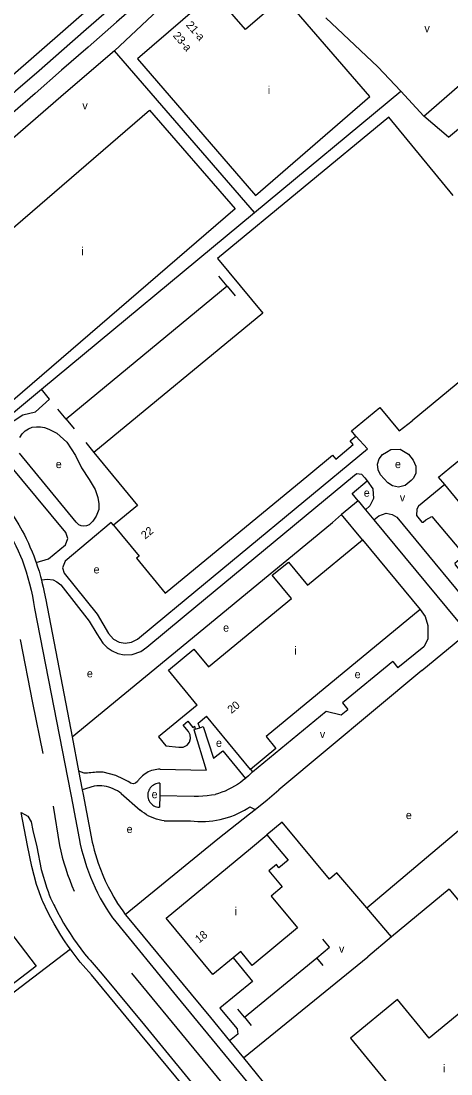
# Model space of a CAD drawing. Extents: x 156097 to 158136, y 385644 to 388348.
# Drawn here: x 156805 to 157020, y 386636 to 387162 of the extents above; entities that cross this region are included whole.
import ezdxf

# ---------------------------------------------------------------- set-up
doc = ezdxf.new("R2010")
doc.units = 0
for name, color, linetype in [('BLT_Basislijn', 7, 'Continuous'), ('BLT_Bebouwing', 7, 'Continuous'), ('BLT_Centroide', 7, 'Continuous'), ('BLT_Huisnummer', 7, 'Continuous'), ('BLT_Huisnummer_reeks', 7, 'Continuous')]:
    doc.layers.add(name, color=color, linetype=linetype)

msp = doc.modelspace()

# ---------------------------------------------------------------- linework, layer by layer
at = {"layer": 'BLT_Basislijn'}
for p, q in [((156921.57, 387066.28), (156851.67, 387147.13)), ((157006.17, 387114.42), (157045.55, 387148.73)), ((156921.57, 387066.28), (156994.69, 387126.94)), ((156815.18, 386977.97), (156921.57, 387066.28)), ((156907.94, 387029.51), (156827.49, 386963.06)), ((156907.94, 387029.51), (156903.87, 387034.43)), ((156907.94, 387029.51), (156912.01, 387024.58)), ((156774.73, 386944.4), (156815.18, 386977.97)), ((156827.49, 386963.06), (156823.42, 386967.99)), ((156827.49, 386963.06), (156831.56, 386958.13)), ((156837.34, 386951.28), (156841.4, 386946.35)), ((156886.56, 386864.54), (156971.62, 386935.07)), ((156973.42, 386922.21), (156965.17, 386915.31)), ((156973.42, 386922.21), (156977.12, 386917.72)), ((156975.66, 386902.77), (156965.17, 386915.31)), ((156977.12, 386917.72), (156981.2, 386912.78)), ((156937.74, 386892.59), (156960.55, 386911.45)), ((156981.2, 386912.78), (157028.02, 386856.23)), ((156929.48, 386885.76), (156937.74, 386892.59)), ((156893.5, 386856.13), (156929.48, 386885.76)), ((156811.8, 386868.47), (156821.48, 386818.91)), ((156830.51, 386804.26), (156893.5, 386856.13)), ((157005.2, 386837.49), (157028.02, 386856.23)), ((156990.73, 386841.92), (156965.6, 386821.21)), ((156990.73, 386841.92), (156993.29, 386838.81)), ((157005.2, 386837.49), (156933.74, 386777.74)), ((156821.48, 386818.91), (156831.03, 386769.38)), ((156965.6, 386821.21), (156968.28, 386817.96)), ((156920.69, 386786.76), (156957.5, 386817.1)), ((156957.5, 386817.1), (156964.97, 386815.21)), ((156830.51, 386804.26), (156833.79, 386787.32)), ((156833.79, 386787.32), (156835.59, 386777.84)), ((156874.59, 386788.06), (156897.42, 386787.68)), ((156841.49, 386779.56), (156835.59, 386777.84)), ((156835.59, 386777.84), (156836.07, 386775.41)), ((156874.42, 386781.08), (156874.33, 386774.94)), ((156927.96, 386772.86), (156933.74, 386777.74)), ((156836.07, 386775.41), (156840.62, 386751.7)), ((156855.08, 386775.94), (156864.57, 386767.64)), ((156874.33, 386774.94), (156874.24, 386769.07)), ((156874.33, 386774.94), (156891.45, 386774.66)), ((156922, 386767.9), (156927.96, 386772.86)), ((156821.02, 386769.55), (156824.27, 386750.03)), ((156831.03, 386769.38), (156831.05, 386769.25)), ((156831.05, 386769.25), (156834.05, 386753.47)), ((156919.21, 386765.71), (156922, 386767.9)), ((156919.31, 386769.26), (156922, 386767.9)), ((156876.6, 386762.34), (156889.69, 386762.31)), ((157018.83, 386728.12), (156990.04, 386704.25)), ((157018.83, 386728.12), (157037.44, 386705.49)), ((156850.82, 386713.62), (156882.63, 386674.75)), ((156990.04, 386704.25), (156977.7, 386718.78)), ((156990.04, 386704.25), (156978.3, 386694.3)), ((156839.55, 386692.59), (156845.59, 386685.61)), ((156916.15, 386643.82), (156978.3, 386694.3)), ((156916.59, 386664.12), (156952.77, 386693.91)), ((156956.02, 386689.96), (156952.77, 386693.91)), ((156882.63, 386674.75), (156928.03, 386619.56)), ((156916.59, 386664.12), (156913.26, 386668.16)), ((156916.59, 386664.12), (156919.92, 386660.08)), ((156909.2, 386652.28), (156916.15, 386643.82)), ((156916.15, 386643.82), (156962.33, 386587.15))]:
    msp.add_line(p, q, dxfattribs=at)
for points in [[(156893.26, 387224.91), (156873.19, 387200.58), (156856.27, 387183.3), (156755.91, 387095.83), (156723.24, 387067.35)], [(156915.13, 387206.65), (156912.2, 387203.9), (156897.9, 387190.48), (156851.67, 387147.13)], [(156864.97, 387181.9), (156848.92, 387167.6), (156837.62, 387157.69), (156825.29, 387146.9), (156814.07, 387137.11), (156802.3, 387126.83), (156793.93, 387119.55), (156777.79, 387105.45), (156745.99, 387077.54), (156731.26, 387064.74), (156721.13, 387056.5)], [(156863.05, 387170.42), (156852.77, 387161.4), (156838.58, 387148.96), (156825.26, 387137.32), (156812.08, 387125.81), (156800.89, 387116.05), (156785.71, 387102.82), (156758.85, 387079.25), (156725.94, 387050.64), (156720.21, 387046.65), (156715.83, 387043.74), (156711.3, 387041.11), (156706.96, 387038.65), (156705.27, 387037.53), (156702.15, 387034.61), (156698.86, 387030.12)], [(156994.69, 387126.94), (156983.23, 387139.01), (156957.32, 387163.53)], [(156851.67, 387147.13), (156827.43, 387126.2), (156771.74, 387078.1), (156736.88, 387048.01), (156705.02, 387020), (156774.73, 386944.4)], [(157018.47, 387103.95), (157054.01, 387133.4)], [(157006.17, 387114.42), (156994.69, 387126.94)], [(157018.47, 387103.95), (157006.17, 387114.42)], [(156812.61, 386891.32), (156818.74, 386893.28), (156827.29, 386900.29), (156828.4, 386903.38), (156827.35, 386906.33), (156798.15, 386941.62), (156796.57, 386945.02), (156795.88, 386948.8), (156796.34, 386953.38), (156798, 386957.66), (156801.65, 386962.4), (156805.97, 386965.18), (156812.2, 386966.59), (156819.25, 386973.04), (156815.18, 386977.97)], [(156804.48, 386953.92), (156805.59, 386955.65), (156807.02, 386957.11), (156808.73, 386958.24), (156810.66, 386958.94), (156812.69, 386959.2), (156814.74, 386959.18), (156816.75, 386958.78), (156818.91, 386957.93), (156822.88, 386956.03), (156827.95, 386951.5), (156832.23, 386944.85), (156835.15, 386938.69), (156839.09, 386932.78), (156842.1, 386927.87), (156843.44, 386923.93), (156843.96, 386920.64), (156843.94, 386917.81), (156842.58, 386914.5), (156840.95, 386912.08), (156839.03, 386910.17), (156837.79, 386909.65), (156836.45, 386909.5), (156835.12, 386909.7), (156833.91, 386910.28), (156832.58, 386911.54), (156804.18, 386945.97)], [(156851.23, 386909.97), (156850.12, 386911.31), (156827.12, 386892.07), (156825.69, 386888.64), (156826.64, 386886.09), (156842.98, 386865.6), (156848.66, 386855.9), (156851.21, 386853.02), (156853.97, 386851.61), (156857, 386851.01), (156860.26, 386851.59), (156863.16, 386853.13), (156877.89, 386865.29), (156882.68, 386869.24), (156978.03, 386948.21), (156972.21, 386954.56)], [(156774.73, 386944.4), (156781.71, 386937.68), (156788.34, 386930.67), (156793.1, 386925.47), (156795.49, 386922.57), (156797.47, 386919.94), (156799.46, 386917.18), (156802.08, 386913.26), (156803.97, 386910.17), (156805.59, 386907.22), (156806.69, 386905.15), (156807.57, 386903.4), (156808.72, 386901), (156809.5, 386899.2), (156810.61, 386896.67), (156811.35, 386894.78), (156812.27, 386892.29), (156812.61, 386891.32)], [(156971.62, 386935.07), (156972.76, 386935.91), (156975.05, 386935.56), (156976.72, 386933.76), (156977.9, 386932.11)], [(156973.42, 386922.21), (156970.38, 386925.9), (156977.9, 386932.11)], [(156977.9, 386932.11), (156980.81, 386928.21), (156981.11, 386923.35), (156979.31, 386919.66), (156977.12, 386917.72)], [(157016.68, 386930.34), (157003.5, 386919.46), (157002.66, 386917.97), (157002.61, 386914.85), (157005.23, 386911.48), (157005.83, 386911.54), (157007.25, 386912.78), (157010.18, 386914.37), (157026.41, 386895.28), (157026.41, 386894.96), (157021.75, 386890.92), (157021.84, 386890.29), (157032.14, 386878.1), (157032.98, 386878.06), (157037.23, 386881.57), (157037.71, 386881.53), (157052.98, 386863.15), (157052.4, 386862.6), (157052.34, 386862.06), (157048.68, 386858.85), (157048.84, 386858.28), (157074.5, 386827.65), (157093.59, 386837.01)], [(156782.29, 386927.92), (156784.31, 386925.85), (156786.27, 386923.72), (156788.18, 386921.53), (156790.02, 386919.3), (156791.81, 386917.01), (156793.52, 386914.68), (156795.18, 386912.3), (156796.76, 386909.87), (156798.28, 386907.4), (156799.73, 386904.9), (156801.11, 386902.35), (156802.42, 386899.76), (156803.66, 386897.14), (156804.82, 386894.49), (156805.57, 386892.68)], [(156965.17, 386915.31), (156960.55, 386911.45)], [(156981.2, 386912.78), (156983.67, 386914.73), (156987.37, 386915.95), (156990.35, 386915.43), (156992.74, 386913.98), (157037.87, 386859.45)], [(156805.57, 386892.68), (156806.62, 386889.71), (156807.6, 386886.71), (156808.5, 386883.69), (156809.32, 386880.65), (156810.06, 386877.59), (156810.73, 386874.51), (156811.32, 386871.41), (156811.8, 386868.47)], [(156812.61, 386891.32), (156813.33, 386889.29), (156814.02, 386887.13), (156814.8, 386884.36), (156815.22, 386882.65)], [(156815.22, 386882.65), (156818.26, 386883.02), (156821, 386882.7), (156822.96, 386881.79), (156824.88, 386880.26), (156839.05, 386862.01), (156842.83, 386855.72), (156845.94, 386851.09), (156848.1, 386848.85), (156850.47, 386847.16), (156853.31, 386845.96), (156856.57, 386845.31), (156860.57, 386845.48), (156864.78, 386846.94), (156867.81, 386849.08), (156886.56, 386864.54)], [(156815.22, 386882.65), (156815.49, 386881.55), (156816.09, 386879.01), (156816.57, 386876.64), (156817.34, 386872.75), (156830.51, 386804.26)], [(157004.43, 386867.87), (157006.94, 386864.34), (157008.25, 386859.91), (157008.25, 386853.13), (157006.14, 386849.31), (156993.29, 386838.81)], [(156804.6, 386852.91), (156810.79, 386821.2), (156815.84, 386795.93)], [(156964.97, 386815.21), (156968.28, 386817.96)], [(156894.29, 386808.74), (156896.03, 386809.36), (156901.24, 386793.66)], [(156892.06, 386808.06), (156891.34, 386807.85), (156897.42, 386787.68)], [(156901.24, 386793.66), (156905.87, 386797.28), (156917.12, 386783.47)], [(156833.79, 386787.32), (156836.46, 386786.3), (156837.33, 386786.31), (156838.21, 386786.33), (156839.09, 386786.37), (156839.96, 386786.45), (156840.83, 386786.53), (156841.69, 386786.65), (156842.55, 386786.79), (156845.89, 386786.79), (156849.07, 386785.97), (156852.29, 386785.1), (156856.08, 386783.33), (156858.74, 386781.97)], [(156874.59, 386788.06), (156873.73, 386788.05), (156872.86, 386787.98), (156871.98, 386787.85), (156871.11, 386787.66), (156870.25, 386787.41), (156869.41, 386787.1), (156868.58, 386786.74), (156867.79, 386786.32), (156867.03, 386785.84), (156866.31, 386785.32), (156865.62, 386784.76), (156864.99, 386784.16), (156864.43, 386783.5)], [(156919.56, 386787.95), (156920.69, 386786.76)], [(156864.43, 386783.5), (156864.17, 386783.2), (156863.92, 386782.89), (156863.67, 386782.58), (156863.43, 386782.26), (156863.2, 386781.93)], [(156917.12, 386783.47), (156916.02, 386782.55), (156914.61, 386781.49), (156913.16, 386780.5), (156911.66, 386779.57), (156910.13, 386778.71), (156908.55, 386777.92), (156906.94, 386777.2), (156905.3, 386776.55), (156903.64, 386775.98), (156901.97, 386775.49)], [(156920.69, 386786.76), (156918.68, 386784.86), (156917.37, 386783.68), (156917.12, 386783.47)], [(156977.7, 386718.78), (157032.01, 386764.67), (157056.78, 386784.72)], [(156855.08, 386775.94), (156854.13, 386776.65), (156853.14, 386777.29), (156852.1, 386777.86), (156851.03, 386778.36), (156849.93, 386778.79), (156848.8, 386779.14), (156847.65, 386779.41), (156846.48, 386779.61), (156845.3, 386779.73), (156844.12, 386779.76), (156842.93, 386779.72), (156841.76, 386779.6), (156841.49, 386779.56)], [(156863.2, 386781.93), (156862.22, 386781.13), (156860.95, 386780.84), (156859.74, 386781.13), (156858.74, 386781.97)], [(156874.42, 386781.08), (156873.73, 386781.05), (156873.05, 386780.94), (156872.38, 386780.76), (156871.74, 386780.49), (156871.13, 386780.16), (156870.57, 386779.76), (156870.05, 386779.29), (156869.59, 386778.77), (156869.2, 386778.2), (156868.87, 386777.59), (156868.62, 386776.95), (156868.44, 386776.28), (156868.34, 386775.59), (156868.32, 386774.9), (156868.39, 386774.21), (156868.52, 386773.53), (156868.74, 386772.87), (156869.03, 386772.24), (156869.39, 386771.65), (156869.82, 386771.11), (156870.31, 386770.61), (156870.85, 386770.18), (156871.43, 386769.81), (156872.06, 386769.51), (156872.72, 386769.29), (156873.39, 386769.14), (156874.08, 386769.08), (156874.24, 386769.07)], [(156891.45, 386774.66), (156893.62, 386774.68), (156895.8, 386774.77), (156897.96, 386774.95), (156900.12, 386775.21), (156901.97, 386775.49)], [(156829.68, 386698.2), (156828.64, 386699.65), (156826.77, 386702.39), (156824.98, 386705.18), (156823.25, 386708), (156821.59, 386710.87), (156819.99, 386713.78), (156818.48, 386716.72), (156815.98, 386721.99), (156815.66, 386722.66), (156812.83, 386730.54), (156810.49, 386739.54), (156808.27, 386750), (156805.04, 386766.42)], [(156805.04, 386766.42), (156808.39, 386764.63), (156810.09, 386761.83), (156810.92, 386757.5), (156812.89, 386749.22), (156815.04, 386737.94), (156817.98, 386728.63)], [(156876.6, 386762.34), (156875.27, 386762.54), (156873.95, 386762.82), (156872.66, 386763.18), (156871.39, 386763.61), (156870.14, 386764.12), (156868.93, 386764.7), (156867.75, 386765.36), (156866.62, 386766.08), (156865.53, 386766.86), (156864.57, 386767.64)], [(156889.69, 386762.31), (156891.54, 386762.11), (156893.4, 386762), (156895.27, 386761.96), (156897.13, 386762), (156898.99, 386762.13), (156900.85, 386762.33), (156902.69, 386762.61), (156904.52, 386762.97), (156906.33, 386763.41), (156908.12, 386763.93), (156909.89, 386764.52), (156911.63, 386765.18), (156913.35, 386765.93), (156915.02, 386766.74), (156916.66, 386767.63), (156918.27, 386768.58), (156919.31, 386769.26)], [(156857.11, 386715.53), (156903.34, 386753.27), (156919.21, 386765.71)], [(156959.04, 386733.16), (156935.54, 386761.59), (156927.88, 386755.37)], [(156834.05, 386753.47), (156834.63, 386750.65), (156835.29, 386747.84), (156836.02, 386745.06), (156836.83, 386742.29), (156837.72, 386739.55), (156838.69, 386736.83), (156839.73, 386734.15), (156840.84, 386731.49), (156842.03, 386728.86), (156843.29, 386726.27), (156844.62, 386723.71), (156846.02, 386721.2), (156847.49, 386718.72), (156849.03, 386716.28), (156850.63, 386713.89), (156850.82, 386713.62)], [(156840.62, 386751.7), (156840.99, 386750), (156841.57, 386747.67), (156842.18, 386745.39)], [(156824.27, 386750.03), (156824.92, 386747.09), (156825.64, 386744.16), (156826.45, 386741.26), (156827.33, 386738.38), (156828.28, 386735.52), (156829.32, 386732.69), (156830.42, 386729.88), (156831.6, 386727.11)], [(156842.18, 386745.39), (156843.57, 386741.09), (156844.68, 386738.09), (156845.87, 386735.19), (156847.13, 386732.28), (156848.6, 386729.28), (156849.83, 386726.98), (156851.42, 386724.1), (156853.27, 386721.04), (156854.48, 386719.2), (156855.8, 386717.35), (156857.11, 386715.53)], [(156977.7, 386718.78), (156962.78, 386736.34), (156959.04, 386733.16)], [(156817.98, 386728.63), (156818.5, 386726.92), (156819.1, 386725.24), (156819.77, 386723.59), (156820.51, 386721.98), (156821.33, 386720.39), (156821.85, 386719.46)], [(156821.85, 386719.46), (156823.24, 386716.68), (156824.7, 386713.93), (156826.22, 386711.22), (156827.82, 386708.55), (156829.49, 386705.92), (156831.22, 386703.34), (156833.01, 386700.8), (156834.88, 386698.31), (156836.8, 386695.87), (156838.79, 386693.48), (156839.55, 386692.59)], [(156857.11, 386715.53), (156858.89, 386713.34), (156876.42, 386692.12), (156899.6, 386663.96), (156909.2, 386652.28)], [(156952.77, 386693.91), (156959.09, 386699.12), (156955.82, 386703.1)], [(156829.68, 386698.2), (156767.55, 386650.84), (156761.9, 386639.25)], [(156944.78, 386558.67), (156926.4, 386581.04), (156860.74, 386660.54), (156840.18, 386685.39), (156836.01, 386690.01), (156834.61, 386691.71), (156832.56, 386694.31), (156830.56, 386696.96), (156829.68, 386698.2)], [(156910.9, 386693.77), (156920.67, 386681.94), (156904.37, 386668.64), (156912.97, 386658.36), (156913.25, 386655.62), (156909.2, 386652.28)], [(156845.59, 386685.61), (156866.65, 386660.17), (156931.32, 386581.16), (156947.74, 386561.4), (156944.78, 386558.67)], [(156860.23, 386686.11), (156880.45, 386661.52), (156949.5, 386577.8)]]:
    msp.add_lwpolyline(points, dxfattribs=at)
msp.add_lwpolyline([(156987.51, 386946.57), (156989.76, 386947.81), (156994.43, 386947.93), (156998.57, 386945.5), (157000.94, 386942.54), (157002.18, 386939.44), (157002.18, 386936.1), (157001.01, 386933.55), (156999.87, 386932.36), (156996.89, 386929.85), (156993.64, 386929.07), (156990.62, 386929.64), (156988.28, 386931.12), (156984.61, 386935.2), (156983.42, 386937.71), (156983.11, 386940.46), (156983.89, 386943.11), (156985.58, 386945.31)], close=True, dxfattribs=at)
at = {"layer": 'BLT_Bebouwing'}
for p, q in [((157019.2, 386938.68), (157066.37, 386977.57)), ((156877.1, 386876), (156948.75, 386935.19)), ((156919.56, 386787.95), (156897.63, 386814.52)), ((156892.06, 386808.06), (156894.29, 386808.74)), ((156932.31, 386798.47), (156919.56, 386787.95)), ((156927.88, 386755.37), (156938.41, 386742.63))]:
    msp.add_line(p, q, dxfattribs=at)
for points in [[(156922.16, 387074.83), (156979.26, 387124.2), (156936.09, 387174.15), (156917.15, 387157.7), (156901.33, 387176.02), (156863.18, 387143.02), (156922.16, 387074.83)], [(156800.99, 386972.36), (156772.74, 387005.15), (156771.43, 387004.01), (156746.54, 387032.81), (156756.3, 387041.25), (156766.82, 387029.07), (156869.16, 387117.49)], [(156869.16, 387117.49), (156912.02, 387068.17), (156800.99, 386972.36)], [(157020.95, 387074.81), (156988.71, 387113.85), (156903.22, 387043.24), (156925.76, 387015.95), (156841.4, 386946.35), (156863.25, 386919.87), (156851.23, 386909.97)], [(157066.37, 386977.57), (157047.13, 387000.88), (157000.31, 386962.25)], [(156972.21, 386954.56), (156970.12, 386957.1), (156984.29, 386968.8)], [(156984.29, 386968.8), (156993.91, 386957.19), (157000.31, 386962.25)], [(156948.75, 386935.19), (156960.62, 386945), (156962.24, 386943.03), (156970.86, 386950.37), (156969.35, 386952.21), (156972.21, 386954.56)], [(157016.68, 386930.34), (157013.61, 386934.07), (157019.2, 386938.68)], [(157047.07, 386893.24), (157045.19, 386895.52), (157041.86, 386892.78), (157040.34, 386894.62), (157043.64, 386897.34), (157041.94, 386899.4), (157038.64, 386896.68), (157036.77, 386898.95), (157040.17, 386901.75), (157016.68, 386930.34)], [(156851.23, 386909.97), (156863.96, 386894.55), (156862.64, 386893.47), (156877.1, 386876)], [(156938.6, 386891.63), (156948.14, 386880.06), (156975.66, 386902.77)], [(156975.66, 386902.77), (157004.43, 386867.87)], [(156930.54, 386884.98), (156938.6, 386891.63)], [(156893.03, 386820.11), (156878.65, 386837.58), (156891.41, 386848.1), (156898.65, 386839.3), (156940.06, 386873.42), (156930.54, 386884.98)], [(157004.43, 386867.87), (156927.43, 386804.38), (156932.31, 386798.47)], [(156893.03, 386820.11), (156873.77, 386804.26), (156877.37, 386799.74), (156883.82, 386799.14), (156885.99, 386799.18), (156887.93, 386800.14), (156889.11, 386801.59), (156889.65, 386803.37), (156889.51, 386805.23), (156888.62, 386806.85)], [(156894.29, 386808.74), (156893.52, 386811.17), (156897.63, 386814.52)], [(156888.62, 386806.85), (156885.94, 386810.09), (156888.3, 386812.04), (156890.86, 386808.97), (156891.59, 386809.57), (156892.06, 386808.06)], [(156910.9, 386693.77), (156900.84, 386685.45), (156877.49, 386713.74), (156919.61, 386748.54), (156927.88, 386755.37)], [(156938.41, 386742.63), (156933.85, 386738.87), (156932.59, 386740.4), (156928.87, 386737.33), (156935.5, 386729.3), (156929.95, 386724.72), (156943.12, 386708.77), (156920.46, 386690.05), (156914.75, 386696.96), (156910.9, 386693.77)], [(157039.69, 386679.08), (157008.89, 386653.73), (156993.01, 386673.02), (156969.52, 386653.68), (157006.07, 386609.22), (157002.5, 386606.28), (157004.19, 386604.23), (156988.5, 386591.31), (156998.23, 386579.49), (157002.08, 386582.67), (157025.46, 386601.92), (157015.82, 386613.63), (157062.16, 386651.78), (157039.69, 386679.08)]]:
    msp.add_lwpolyline(points, dxfattribs=at)
msp.add_lwpolyline([(156693.61, 386700.76), (156719.8, 386720.69), (156712.32, 386730.44), (156735.93, 386748.43), (156739.28, 386750.71), (156741.85, 386752.21), (156744.66, 386753.54), (156745.65, 386753.97), (156750.97, 386755.69), (156760.83, 386757.52), (156812.59, 386689.74), (156789.57, 386672.17), (156756.91, 386715), (156712.3, 386681), (156704.26, 386691.55), (156701.97, 386689.8)], close=True, dxfattribs=at)

# ---------------------------------------------------------------- texts
at = {"layer": 'BLT_Centroide'}
for s, p in [('v', (157006.52, 387156.32)), ('i', (156928.3, 387125.44)), ('v', (156835.67, 387117.76)), ('i', (156835.12, 387044.94)), ('e', (156822.37, 386938.55)), ('e', (156991.8, 386938.55)), ('e', (156976.21, 386924.26)), ('v', (156994.23, 386921.89)), ('e', (156841.26, 386885.91)), ('e', (156905.96, 386856.84)), ('i', (156941.56, 386845.38)), ('e', (156837.92, 386833.97)), ('e', (156971.64, 386833.57)), ('v', (156954.28, 386803.66)), ('e', (156902.4, 386799.26)), ('e', (156870.24, 386773.6)), ('e', (156997.24, 386763.17)), ('e', (156857.76, 386756.19)), ('i', (156911.71, 386715.13)), ('v', (156963.84, 386696.39)), ('i', (157015.84, 386636.55))]:
    msp.add_text(s, height=4, dxfattribs=at).set_placement(p)
at = {"layer": 'BLT_Huisnummer'}
for s, rotation, p in [('20', 39.5913, (156910.14, 386815.67)), ('18', 39.4652, (156893.97, 386700.94))]:
    msp.add_text(s, height=4, rotation=rotation, dxfattribs=at).set_placement(p)
at = {"layer": 'BLT_Huisnummer_reeks'}
for s, rotation, p in [('21-a', 310.8167, (156887.18, 387159.84)), ('23-a', 310.8167, (156880.66, 387154.52)), ('22', 39.4645, (156867, 386902.82))]:
    msp.add_text(s, height=4, rotation=rotation, dxfattribs=at).set_placement(p)

doc.saveas('drawing.dxf')
